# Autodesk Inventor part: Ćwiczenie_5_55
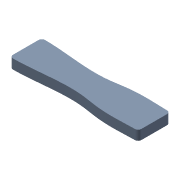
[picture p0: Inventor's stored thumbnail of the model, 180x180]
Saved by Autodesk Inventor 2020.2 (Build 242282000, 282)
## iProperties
Created: 2005-05
Part Number: Ćwiczenie_5_55
Document SubType Name: Modeling
Designer: F.Stasiak
Manufacturer: Standard
Standards Organization: Custom
Density: 1 g/cm^3
Material: Ogólny
Appearance: Stalowoniebieska - jasna
Manager: www.cadconsulting.pl
Company: Fabian Stasiak CAD Consulting
Author: F.Stasiak
Subject: Zbiór ćwiczeń. Autodesk Inventor 2020. Kurs podstawowy
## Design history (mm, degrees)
sketch "Szkic1"
  geometry: L1 (-100, 25)-(100, 25); L2 (100, 25)-(100, -25); L3 (100, -25)-(-100, -25); L4 (-100, -25)-(-100, 25); L5 (0, 25)-(0, -25); L6 (-120.429, 25)-(-79.571, 25); L7 (79.571, 25)-(120.429, 25); L8 (-100, 0)-(100, 0); L9 (-120.429, -25)-(-79.571, -25); L10 (79.571, -25)-(120.429, -25); A1 r 559.729 centre (-100, -534.729) between (-79.585, 24.628) and (-120.415, 24.628); A2 r 211.524 centre (100, 236.524) between (79.666, 25.98) and (120.334, 25.98); A3 r 559.729 centre (-100, 534.729) between (-120.415, -24.628) and (-79.585, -24.628); A4 r 211.524 centre (100, -236.524) between (120.334, -25.98) and (79.666, -25.98); 8 further points
  constraints: 20 end point, 13 symmetric about line, 11 midpoint, 6 horizontal, 4 centre point, 4 point on circle, 3 perpendicular, 2 parallel, 2 point on line, 1 coincident, 16 other
  dimensions: "d0" = 200 distance of L2.end L3.end; "d1" = 50 distance of L3.end L1.start; "d2" = 10 dimension on L6.start L6.end; "d3" = 10 dimension on L7.start L7.end; "d4" = 40 distance of point (0, -20) point (0, 20); "d5" = 40 distance from line of point (-60, -22.902) L4; "d6" = 60 distance from line of L2 point (40, -25)
extrude "Wyciągnięcie proste1" new body sketch "Szkic1" distance "d7" = 15; taper "d8" = 0 deg
sketch "Początek"
  geometry: L1 (100, 25)-(100, 25); L2 (100, 25)-(75, 25); L3 (75, 25)-(75, -25); L4 (75, -25)-(100, -25); A1 r 25 centre (75, 0) between (75, 25) and (75, -25)
  constraints: 8 end point, 2 point on circle, 2 tangent, 1 centre point, 1 parallel, 1 perpendicular
  dimensions: "d13" = 25 distance of L1.end L2.end
sketch "Koniec"
  geometry: L1 (-100, -25)-(-100, 25) reference; L2 (-100, 25)-(-50, 30); L3 (-50, 30)-(-50, -30); L4 (-50, -30)-(-100, -25); L5 (-100, 0)-(-50, 0); A1 r 31.906 centre (-60.861, 0) between (-50, -30) and (-50, 30)
  constraints: 8 end point, 2 midpoint, 2 point on circle, 1 centre point, 1 horizontal, 1 parallel
  dimensions: "d14" = 60 distance of L2.end L3.end; "d15" = 50 distance between parallel lines of L3 L1
node "Punkt konstrukcyjny1"
node "Punkt konstrukcyjny2"
sketch "Prowadnica"
  geometry: 3 further points
  constraints: 3 other
fillet "Zaokrąglenie1" dims "d24" = 5
node "Bryła1"
node "Korpusy bryłowe"
node "Korpusy powierzchniowe"
